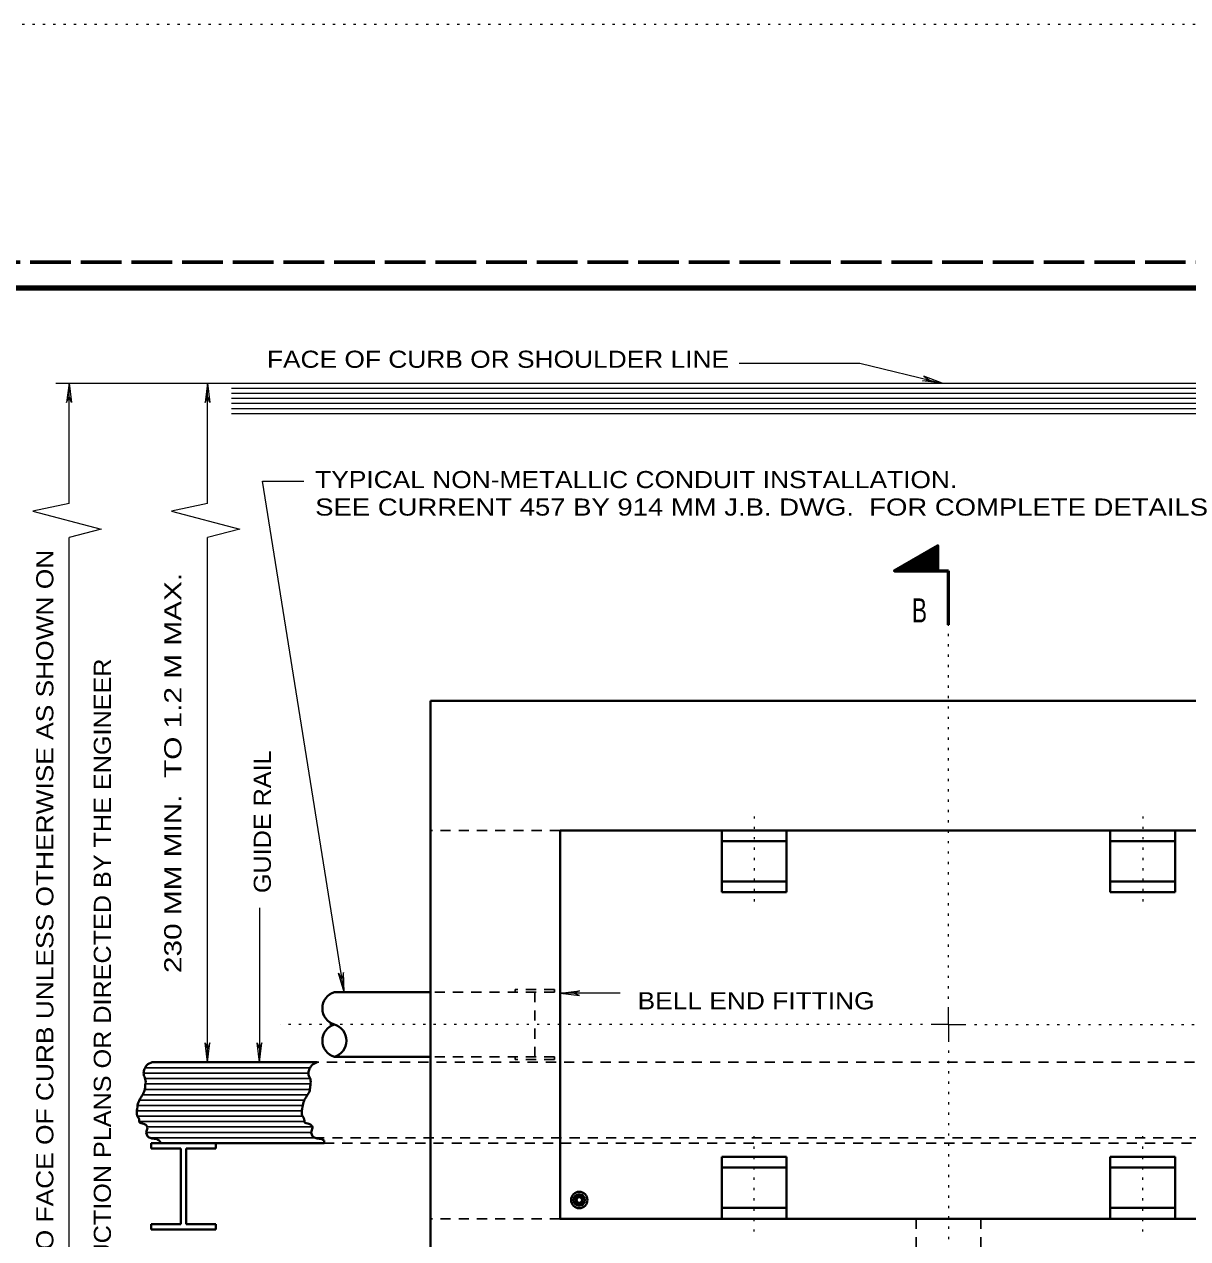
# Model space of a CAD drawing. Extents: x 312583 to 312854, y 144419 to 144597.
# Drawn here: x 312766.4 to 312818.1, y 144542.9 to 144596.8 of the extents above; entities that cross this region are included whole.
import ezdxf
from ezdxf.enums import TextEntityAlignment as Align

# ---------------------------------------------------------------- set-up
doc = ezdxf.new("R2010")
doc.units = 0
doc.header["$LTSCALE"] = 0.3
for name, pattern in [('DOTTED', [1.5, 0.3, -1.2]), ('LONG_DASHED', [7.5, 6, -1.5]), ('SHORT_DASHED', [2.7, 1.5, -1.2])]:
    doc.linetypes.add(name, pattern=pattern)
doc.layers.add('1', color=7, linetype='Continuous', lineweight=13)
doc.layers.add('63', color=7, linetype='DOTTED', lineweight=13)

msp = doc.modelspace()

# ---------------------------------------------------------------- linework, layer by layer
at = {"layer": '1', "linetype": 'LONG_DASHED', "lineweight": 60}
msp.add_line((312851.75, 144586.2246), (312583.526, 144586.2246), dxfattribs=at)
at = {"layer": '1', "lineweight": 158}
msp.add_line((312616.5, 144585.0846), (312849, 144585.0846), dxfattribs=at)
at = {"layer": '1'}
for p, q in [((312767.8328, 144580.8522), (312770.8698, 144580.8522)), ((312768.4232, 144580.8522), (312768.3158, 144579.9859)), ((312768.4232, 144580.8522), (312768.5305, 144579.9859)), ((312768.4232, 144575.5009), (312768.4232, 144580.8522)), ((312774.5749, 144580.8522), (312774.4676, 144579.9859)), ((312774.5749, 144580.8522), (312774.6823, 144579.9859)), ((312774.5749, 144575.5009), (312774.5749, 144580.8522)), ((312806.3258, 144580.9519), (312806.6248, 144580.9902)), ((312807.1998, 144580.8522), (312806.3258, 144580.9519)), ((312806.3795, 144581.1589), (312806.6248, 144580.9902)), ((312807.1998, 144580.8522), (312806.3795, 144581.1589)), ((312775.6331, 144580.6299), (312838.8555, 144580.6299)), ((312775.6331, 144580.4076), (312838.8555, 144580.4076)), ((312768.3158, 144579.9859), (312768.4232, 144580.2619)), ((312768.5305, 144579.9859), (312768.4232, 144580.2619)), ((312774.4676, 144579.9859), (312774.5749, 144580.2619)), ((312774.6823, 144579.9859), (312774.5749, 144580.2619)), ((312775.6331, 144580.1852), (312838.8555, 144580.1852)), ((312775.6331, 144579.9552), (312838.8555, 144579.9552)), ((312775.6331, 144579.7329), (312838.8555, 144579.7329)), ((312775.6331, 144579.5106), (312838.8555, 144579.5106)), ((312768.4232, 144532.9662), (312768.4232, 144573.9982)), ((312774.5749, 144550.6992), (312774.5749, 144573.9982)), ((312776.8826, 144557.5609), (312776.8826, 144550.6992)), ((312780.3895, 144554.6476), (312780.5352, 144554.3946)), ((312780.6348, 144553.8119), (312780.3895, 144554.6476)), ((312780.6042, 144554.6859), (312780.5352, 144554.3946)), ((312780.6348, 144553.8119), (312780.6042, 144554.6859)), ((312790.2258, 144553.7659), (312791.0922, 144553.8732)), ((312791.0922, 144553.8732), (312790.8162, 144553.7659)), ((312792.9015, 144553.7659), (312790.2258, 144553.7659)), ((312790.2258, 144553.7659), (312791.0922, 144553.6586)), ((312791.0922, 144553.6586), (312790.8162, 144553.7659)), ((312807.4758, 144552.3706), (312807.4758, 144553.1372)), ((312807.4758, 144552.3706), (312806.7092, 144552.3706)), ((312807.4758, 144552.3706), (312808.2425, 144552.3706)), ((312807.4758, 144552.3706), (312807.4758, 144551.6039)), ((312774.4676, 144551.5656), (312774.5749, 144551.2896)), ((312774.5749, 144550.6992), (312774.4676, 144551.5656)), ((312774.6823, 144551.5656), (312774.5749, 144551.2896)), ((312774.5749, 144550.6992), (312774.6823, 144551.5656)), ((312776.7753, 144551.5656), (312776.8826, 144551.2896)), ((312776.8826, 144550.6992), (312776.7753, 144551.5656)), ((312776.9899, 144551.5656), (312776.8826, 144551.2896)), ((312776.8826, 144550.6992), (312776.9899, 144551.5656))]:
    msp.add_line(p, q, dxfattribs=at)
at = {"layer": '1', "lineweight": 35}
for p, q in [((312806.7935, 144572.5186), (312806.3642, 144573.2622)), ((312806.8165, 144572.5262), (312806.3872, 144573.2699)), ((312806.8472, 144572.5262), (312806.4025, 144573.2852)), ((312806.8702, 144572.5186), (312806.4255, 144573.2929)), ((312806.9008, 144572.5186), (312806.4485, 144573.3082)), ((312806.9238, 144572.5186), (312806.4638, 144573.3159)), ((312806.9545, 144572.5186), (312806.4868, 144573.3312)), ((312806.9852, 144572.5186), (312806.5098, 144573.3389)), ((312807.0005, 144572.5416), (312806.5252, 144573.3542)), ((312807.0005, 144572.5952), (312806.5558, 144573.3619)), ((312807.0005, 144572.6336), (312806.5712, 144573.3772)), ((312807.0005, 144572.6872), (312806.5942, 144573.3849)), ((312807.0005, 144572.7332), (312806.6172, 144573.4002)), ((312807.0005, 144572.7792), (312806.6325, 144573.4156)), ((312807.0005, 144572.8252), (312806.6555, 144573.4232)), ((312807.0005, 144572.8789), (312806.6785, 144573.4386)), ((312807.0005, 144572.9249), (312806.6938, 144573.4539)), ((312807.0005, 144572.9709), (312806.7168, 144573.4616)), ((312807.0005, 144573.0246), (312806.7322, 144573.4769)), ((312807.0005, 144573.0706), (312806.7552, 144573.4846)), ((312807.0005, 144573.1166), (312806.7782, 144573.4999)), ((312807.0005, 144573.1702), (312806.7935, 144573.5076)), ((312807.0005, 144573.2162), (312806.8242, 144573.5229)), ((312807.0005, 144573.2622), (312806.8395, 144573.5306)), ((312807.0005, 144573.3082), (312806.8625, 144573.5459)), ((312807.0005, 144573.3619), (312806.8855, 144573.5536)), ((312807.0005, 144573.4002), (312806.9008, 144573.5689)), ((312807.0005, 144573.4539), (312806.9238, 144573.5766)), ((312807.0005, 144573.4999), (312806.9468, 144573.5919)), ((312807.0005, 144573.5536), (312806.9622, 144573.6072)), ((312807.0005, 144573.5996), (312806.9852, 144573.6149)), ((312805.5438, 144572.5186), (312805.4288, 144572.7256)), ((312805.5745, 144572.5186), (312805.4518, 144572.7332)), ((312805.5975, 144572.5186), (312805.4672, 144572.7486)), ((312805.6282, 144572.5186), (312805.4902, 144572.7562)), ((312805.6588, 144572.5186), (312805.5132, 144572.7716)), ((312805.6818, 144572.5186), (312805.5285, 144572.7792)), ((312805.7125, 144572.5186), (312805.5592, 144572.7946)), ((312805.7355, 144572.5186), (312805.5745, 144572.8022)), ((312805.7662, 144572.5186), (312805.5975, 144572.8176)), ((312805.7968, 144572.5186), (312805.6205, 144572.8252)), ((312805.8198, 144572.5186), (312805.6358, 144572.8406)), ((312805.8505, 144572.5186), (312805.6588, 144572.8482)), ((312805.8735, 144572.5186), (312805.6818, 144572.8636)), ((312805.9042, 144572.5186), (312805.6972, 144572.8789)), ((312805.9272, 144572.5186), (312805.7202, 144572.8866)), ((312805.9578, 144572.5186), (312805.7432, 144572.9019)), ((312805.9885, 144572.5186), (312805.7585, 144572.9172)), ((312806.0192, 144572.5186), (312805.7815, 144572.9249)), ((312806.0422, 144572.5186), (312805.8045, 144572.9402)), ((312806.0652, 144572.5186), (312805.8275, 144572.9479)), ((312806.0958, 144572.5186), (312805.8428, 144572.9632)), ((312806.1265, 144572.5186), (312805.8658, 144572.9709)), ((312806.1495, 144572.5186), (312805.8888, 144572.9862)), ((312806.1802, 144572.5186), (312805.9042, 144572.9939)), ((312806.2108, 144572.5186), (312805.9272, 144573.0092)), ((312806.2338, 144572.5186), (312805.9502, 144573.0169)), ((312806.2645, 144572.5186), (312805.9655, 144573.0322)), ((312806.2952, 144572.5186), (312805.9885, 144573.0399)), ((312806.3182, 144572.5186), (312806.0115, 144573.0552)), ((312806.3488, 144572.5262), (312806.0268, 144573.0706)), ((312806.3718, 144572.5186), (312806.0575, 144573.0782)), ((312806.4025, 144572.5186), (312806.0728, 144573.0936)), ((312806.4255, 144572.5186), (312806.0958, 144573.1012)), ((312806.4562, 144572.5186), (312806.1188, 144573.1166)), ((312806.4868, 144572.5186), (312806.1342, 144573.1242)), ((312806.5175, 144572.5186), (312806.1572, 144573.1396)), ((312806.5405, 144572.5186), (312806.1802, 144573.1472)), ((312806.5635, 144572.5186), (312806.1955, 144573.1626)), ((312806.5942, 144572.5262), (312806.2185, 144573.1702)), ((312806.6248, 144572.5186), (312806.2415, 144573.1856)), ((312806.6478, 144572.5186), (312806.2568, 144573.1932)), ((312806.6785, 144572.5186), (312806.2798, 144573.2086)), ((312806.7092, 144572.5186), (312806.3028, 144573.2239)), ((312806.7322, 144572.5186), (312806.3258, 144573.2316)), ((312806.7628, 144572.5186), (312806.3412, 144573.2469)), ((312805.0992, 144572.5186), (312805.0992, 144572.5339)), ((312805.1298, 144572.5186), (312805.1222, 144572.5416)), ((312805.1605, 144572.5186), (312805.1375, 144572.5569)), ((312805.1835, 144572.5186), (312805.1605, 144572.5646)), ((312805.2142, 144572.5186), (312805.1835, 144572.5799)), ((312805.2372, 144572.5186), (312805.1988, 144572.5876)), ((312805.2678, 144572.5186), (312805.2218, 144572.6029)), ((312805.2985, 144572.5186), (312805.2448, 144572.6106)), ((312805.3292, 144572.5186), (312805.2602, 144572.6259)), ((312805.3522, 144572.5186), (312805.2832, 144572.6336)), ((312805.3752, 144572.5186), (312805.3062, 144572.6489)), ((312805.4058, 144572.5186), (312805.3292, 144572.6566)), ((312805.4288, 144572.5186), (312805.3445, 144572.6719)), ((312805.4595, 144572.5186), (312805.3675, 144572.6872)), ((312805.4902, 144572.5186), (312805.3905, 144572.6949)), ((312805.5208, 144572.5186), (312805.4058, 144572.7102))]:
    msp.add_line(p, q, dxfattribs=at)
at = {"layer": '1', "lineweight": 53}
for p in [(312807.0005, 144572.5186), (312807.4758, 144570.1266)]:
    msp.add_line(p, (312807.4758, 144572.5186), dxfattribs=at)
at = {"layer": '1', "linetype": 'DOTTED'}
for p, q in [((312807.4758, 144553.5206), (312807.4758, 144570.1266)), ((312798.8508, 144561.6166), (312798.8508, 144557.4842)), ((312816.1008, 144561.6166), (312816.1008, 144557.4842)), ((312806.3258, 144552.3706), (312777.8058, 144552.3706)), ((312808.6258, 144552.3706), (312837.7285, 144552.3706)), ((312807.4758, 144551.2206), (312807.4758, 144538.5706)), ((312798.8508, 144543.1782), (312798.8508, 144547.4332)), ((312816.1008, 144543.1782), (312816.1008, 144547.4332))]:
    msp.add_line(p, q, dxfattribs=at)
at = {"layer": '1', "lineweight": 40}
for p, q in [((312784.4758, 144566.7456), (312830.4758, 144566.7456)), ((312784.4758, 144566.7456), (312784.4758, 144537.9956)), ((312790.2258, 144560.9956), (312824.7258, 144560.9956)), ((312797.4095, 144560.9956), (312797.4095, 144558.2432)), ((312800.2845, 144560.9956), (312800.2845, 144558.2432)), ((312814.6595, 144560.9956), (312814.6595, 144558.2432)), ((312817.5345, 144560.9956), (312817.5345, 144558.2432)), ((312797.4095, 144560.5202), (312800.2845, 144560.5202)), ((312817.5345, 144560.5202), (312814.6595, 144560.5202)), ((312797.4095, 144558.7262), (312800.2845, 144558.7262)), ((312817.5345, 144558.7262), (312814.6595, 144558.7262)), ((312797.4095, 144558.2432), (312800.2845, 144558.2432)), ((312817.5345, 144558.2432), (312814.6595, 144558.2432)), ((312784.4758, 144553.8119), (312780.2055, 144553.8119)), ((312784.4758, 144550.9369), (312780.2055, 144550.9369)), ((312772.0679, 144546.8659), (312772.0679, 144547.1036)), ((312773.3866, 144546.8659), (312772.0679, 144546.8659)), ((312772.4206, 144547.2262), (312772.5126, 144547.1036)), ((312773.3866, 144543.5079), (312773.3866, 144546.8659)), ((312773.6243, 144543.5079), (312773.6243, 144546.8659)), ((312774.9429, 144546.8659), (312773.6243, 144546.8659)), ((312774.9429, 144546.8659), (312774.9429, 144547.1036)), ((312779.7455, 144547.2262), (312779.7455, 144547.1036)), ((312797.4095, 144546.5056), (312800.2845, 144546.5056)), ((312797.4095, 144543.7456), (312797.4095, 144546.5056)), ((312800.2845, 144543.7456), (312800.2845, 144546.5056)), ((312817.5345, 144546.5056), (312814.6595, 144546.5056)), ((312814.6595, 144543.7456), (312814.6595, 144546.5056)), ((312817.5345, 144543.7456), (312817.5345, 144546.5056)), ((312797.4095, 144546.0226), (312800.2845, 144546.0226)), ((312817.5345, 144546.0226), (312814.6595, 144546.0226)), ((312797.4095, 144544.2286), (312800.2845, 144544.2286)), ((312817.5345, 144544.2286), (312814.6595, 144544.2286)), ((312773.3866, 144543.5079), (312772.0679, 144543.5079)), ((312772.0679, 144543.2702), (312772.0679, 144543.5079)), ((312774.9429, 144543.2702), (312772.0679, 144543.2702)), ((312774.9429, 144543.5079), (312773.6243, 144543.5079)), ((312774.9429, 144543.2702), (312774.9429, 144543.5079))]:
    msp.add_line(p, q, dxfattribs=at)
at = {"layer": '1', "linetype": 'SHORT_DASHED', "lineweight": 25}
for p, q in [((312790.2258, 144560.9956), (312784.4758, 144560.9956)), ((312789.9728, 144553.9346), (312788.2402, 144553.9346)), ((312788.2402, 144553.8119), (312788.2402, 144553.9346)), ((312789.9728, 144553.8119), (312789.9728, 144553.9346)), ((312789.9728, 144553.8119), (312784.4758, 144553.8119)), ((312789.1065, 144553.8119), (312789.1065, 144550.9369)), ((312833.7878, 144550.6992), (312779.4465, 144550.6992)), ((312789.9728, 144550.9369), (312784.4758, 144550.9369)), ((312788.2402, 144550.9369), (312788.2402, 144550.8142)), ((312789.9728, 144550.8142), (312788.2402, 144550.8142)), ((312789.9728, 144550.9369), (312789.9728, 144550.8142)), ((312779.3085, 144547.3412), (312833.8722, 144547.3412)), ((312779.7455, 144547.1036), (312833.4888, 144547.1036)), ((312790.2258, 144543.7456), (312784.4758, 144543.7456)), ((312806.0345, 144543.7456), (312806.0345, 144532.9662)), ((312808.9095, 144543.7456), (312808.9095, 144532.9662))]:
    msp.add_line(p, q, dxfattribs=at)
at = {"layer": '1'}
for points in [[(312798.1838, 144581.7416), (312803.5428, 144581.7416), (312807.1998, 144580.8522)], [(312770.8698, 144580.8522), (312842.3325, 144580.8522), (312844.9146, 144580.8522)], [(312780.6348, 144553.8119), (312777.0085, 144576.4976), (312778.8562, 144576.4976)], [(312768.4232, 144575.5009), (312766.8208, 144575.1636), (312769.8492, 144574.3662), (312768.4232, 144573.9982)], [(312774.5749, 144575.5009), (312772.9726, 144575.1636), (312776.0086, 144574.3662), (312774.5749, 144573.9982)]]:
    msp.add_lwpolyline(points, dxfattribs=at)
at = {"layer": '1', "lineweight": 53}
msp.add_lwpolyline([(312807.0005, 144572.5186), (312807.0005, 144573.6302), (312805.0838, 144572.5186)], close=True, dxfattribs=at)
at = {"layer": '1', "lineweight": 40}
for points in [[(312790.2258, 144560.9956), (312790.2258, 144543.7456), (312824.7258, 144543.7456)], [(312779.4465, 144550.6992), (312777.4319, 144550.6992), (312772.1216, 144550.6992)], [(312779.7455, 144547.1036), (312777.4319, 144547.1036), (312772.0679, 144547.1036)]]:
    msp.add_lwpolyline(points, dxfattribs=at)
at = {"layer": '1', "lineweight": 25}
for points in [[(312779.0632, 144550.2162), (312777.4319, 144550.2162), (312771.7383, 144550.2162)], [(312779.1245, 144550.4539), (312777.4319, 144550.4539), (312771.7996, 144550.4539)], [(312779.1245, 144549.9786), (312777.4319, 144549.9786), (312771.7996, 144549.9786)], [(312779.1475, 144549.7409), (312777.4319, 144549.7409), (312771.8149, 144549.7409)], [(312778.8868, 144549.0202), (312777.4319, 144549.0202), (312771.5543, 144549.0202)], [(312779.0248, 144549.2579), (312777.4319, 144549.2579), (312771.6846, 144549.2579)], [(312779.1168, 144549.4956), (312777.4319, 144549.4956), (312771.7843, 144549.4956)], [(312778.7642, 144548.5372), (312777.4319, 144548.5372), (312771.4393, 144548.5372)], [(312778.8025, 144548.7826), (312777.4319, 144548.7826), (312771.4699, 144548.7826)], [(312778.7948, 144548.2996), (312777.4319, 144548.2996), (312771.4699, 144548.2996)], [(312778.8332, 144548.0619), (312777.4319, 144548.0619), (312771.5466, 144548.0619)], [(312779.2088, 144547.5789), (312777.4319, 144547.5789), (312771.8763, 144547.5789)], [(312779.2318, 144547.8242), (312777.4319, 144547.8242), (312771.8993, 144547.8242)], [(312779.3085, 144547.3412), (312777.4319, 144547.3412), (312772.0373, 144547.3412)]]:
    msp.add_lwpolyline(points, dxfattribs=at)
at = {"layer": '1', "lineweight": 40}
for radius in [0.3629, 0.2541, 0.1779, 0.1245]:
    msp.add_circle((312791.0794, 144544.5827), radius, dxfattribs=at)
for centre, start, end in [((312780.4255, 144553.0922), 107.01939, 252.98061), ((312780.4255, 144551.6547), 107.01939, 252.98061), ((312779.9855, 144551.6547), 287.01939, 72.98061)]:
    msp.add_arc(centre, 0.7517, start, end, dxfattribs=at)
for points in [[(312772.1216, 144550.6992), (312771.8763, 144550.5689), (312771.7996, 144550.4539), (312771.7383, 144550.2699), (312771.7383, 144550.1396), (312771.7689, 144550.0629), (312771.8073, 144549.9479), (312771.8303, 144549.8176), (312771.8073, 144549.6796), (312771.7996, 144549.5799), (312771.7766, 144549.4419), (312771.7153, 144549.3039), (312771.5926, 144549.1046), (312771.4853, 144548.8592), (312771.4393, 144548.5602), (312771.4469, 144548.3379), (312771.5389, 144548.1616), (312771.5466, 144548.0389), (312771.7459, 144547.9622), (312771.8609, 144547.8932), (312771.8993, 144547.8242), (312771.8609, 144547.6402), (312771.9529, 144547.3719), (312772.1063, 144547.3182), (312772.3209, 144547.2799), (312772.4206, 144547.2262)], [(312779.4465, 144550.6992), (312779.2088, 144550.5689), (312779.1245, 144550.4539), (312779.0632, 144550.2699), (312779.0632, 144550.1396), (312779.0938, 144550.0629), (312779.1398, 144549.9479), (312779.1552, 144549.8176), (312779.1398, 144549.6796), (312779.1245, 144549.5799), (312779.1092, 144549.4419), (312779.0478, 144549.3039), (312778.9175, 144549.1046), (312778.8178, 144548.8592), (312778.7642, 144548.5602), (312778.7795, 144548.3379), (312778.8715, 144548.1616), (312778.8792, 144548.0389), (312779.0785, 144547.9622), (312779.1858, 144547.8932), (312779.2318, 144547.8242), (312779.1858, 144547.6402), (312779.2855, 144547.3719), (312779.4388, 144547.3182), (312779.6535, 144547.2799), (312779.7455, 144547.2262)]]:
    msp.add_spline(points, degree=3, dxfattribs=at)
at = {"layer": '63'}
msp.add_line((312601.2, 144596.7846), (312853.5, 144596.7846), dxfattribs=at)

# ---------------------------------------------------------------- texts
at = {"layer": '1'}
for s, width, p in [('FACE OF CURB OR SHOULDER LINE', 1.15, (312777.2113, 144581.5324)), ('TYPICAL NON-METALLIC CONDUIT INSTALLATION.', 1.15, (312779.3545, 144576.1899)), ('SEE CURRENT 457 BY 914 MM J.B. DWG.  FOR COMPLETE DETAILS', 1.2, (312779.3545, 144574.9699)), ('BELL END FITTING', 1.15, (312793.6705, 144553.049))]:
    msp.add_text(s, height=0.76, dxfattribs=dict(at, width=width)).set_placement(p)
for s, width, p in [('  FOUNDATION TO FACE OF CURB UNLESS OTHERWISE AS SHOWN ON', 1.15, (312767.7278, 144532.9367)), ('230 MM MIN.  TO 1.2 M MAX.', 1.3, (312773.4117, 144554.6592)), ('CONSTRUCTION PLANS OR DIRECTED BY THE ENGINEER', 1.1, (312770.2831, 144537.1313)), ('GUIDE RAIL', 1.1, (312777.3854, 144558.2092))]:
    msp.add_text(s, height=0.76, rotation=90, dxfattribs=dict(at, width=width)).set_placement(p)
at = {"layer": '1', "width": 0.7}
msp.add_text('B', height=1.07, dxfattribs=at).set_placement((312806.1864, 144570.2261), align=Align.CENTER)

doc.saveas('drawing.dxf')
